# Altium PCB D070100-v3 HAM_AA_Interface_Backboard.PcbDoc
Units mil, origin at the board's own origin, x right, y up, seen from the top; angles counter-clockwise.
Board outline 2600 x 10000 mil, 6 copper layers (Top Layer, InternalPlane1, MidLayer1, InternalPlane3, InternalPlane4, Bottom Layer), stack 92.2 mil thick; 10 components, 66 nets, 166 pads, 190 vias.
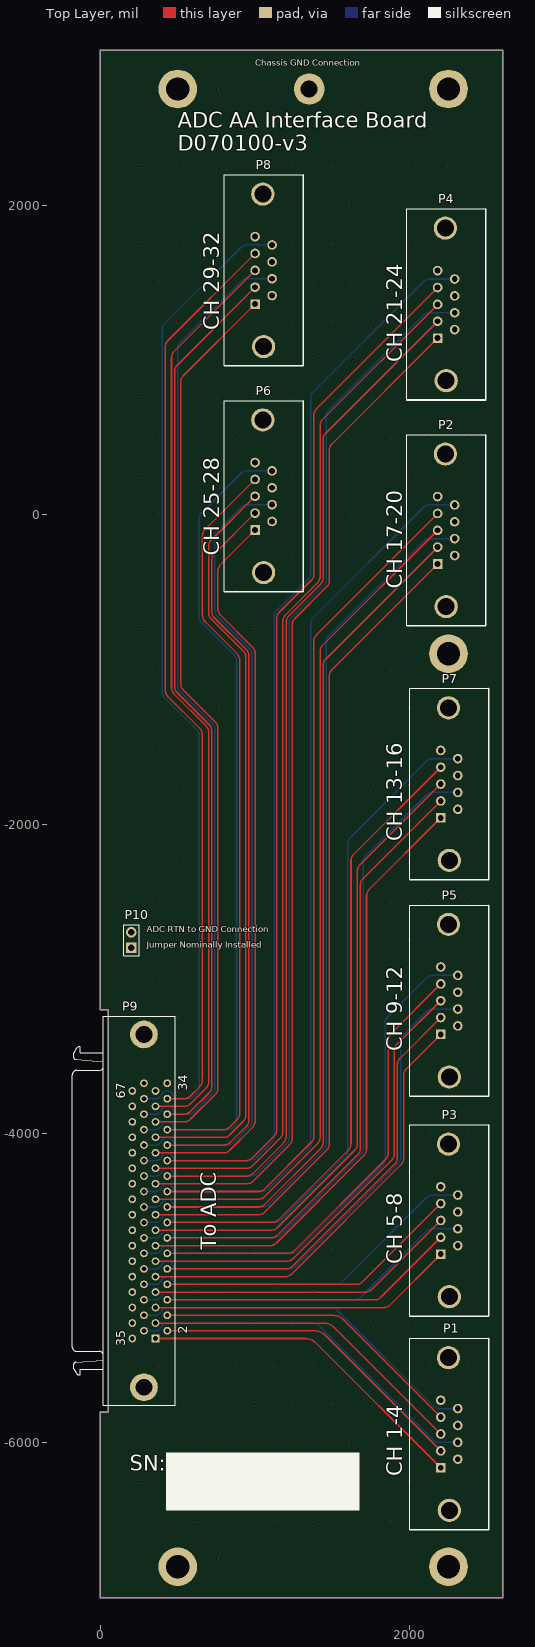
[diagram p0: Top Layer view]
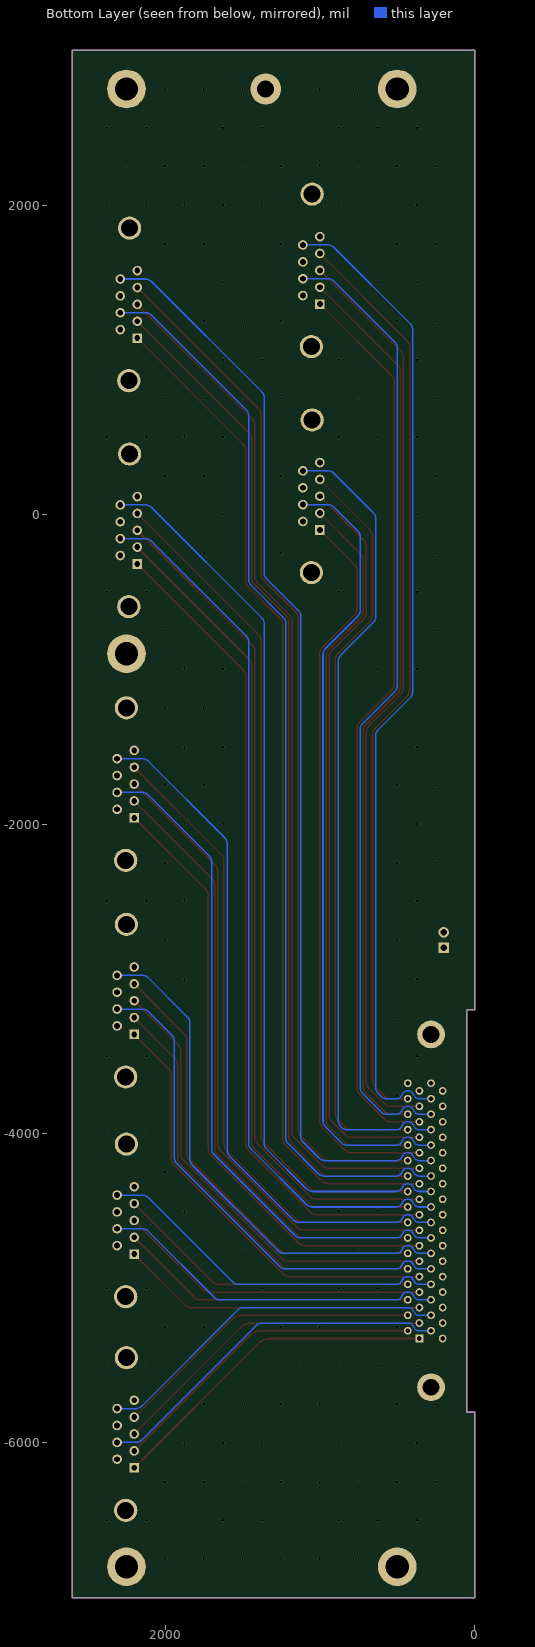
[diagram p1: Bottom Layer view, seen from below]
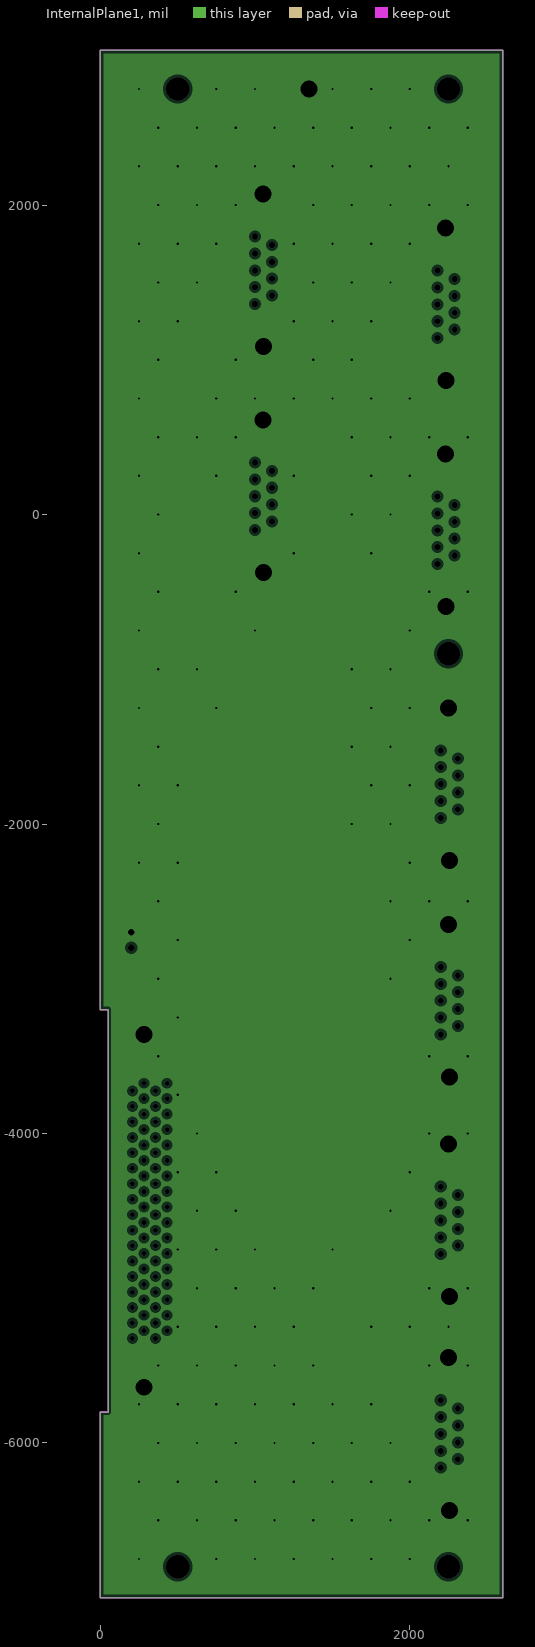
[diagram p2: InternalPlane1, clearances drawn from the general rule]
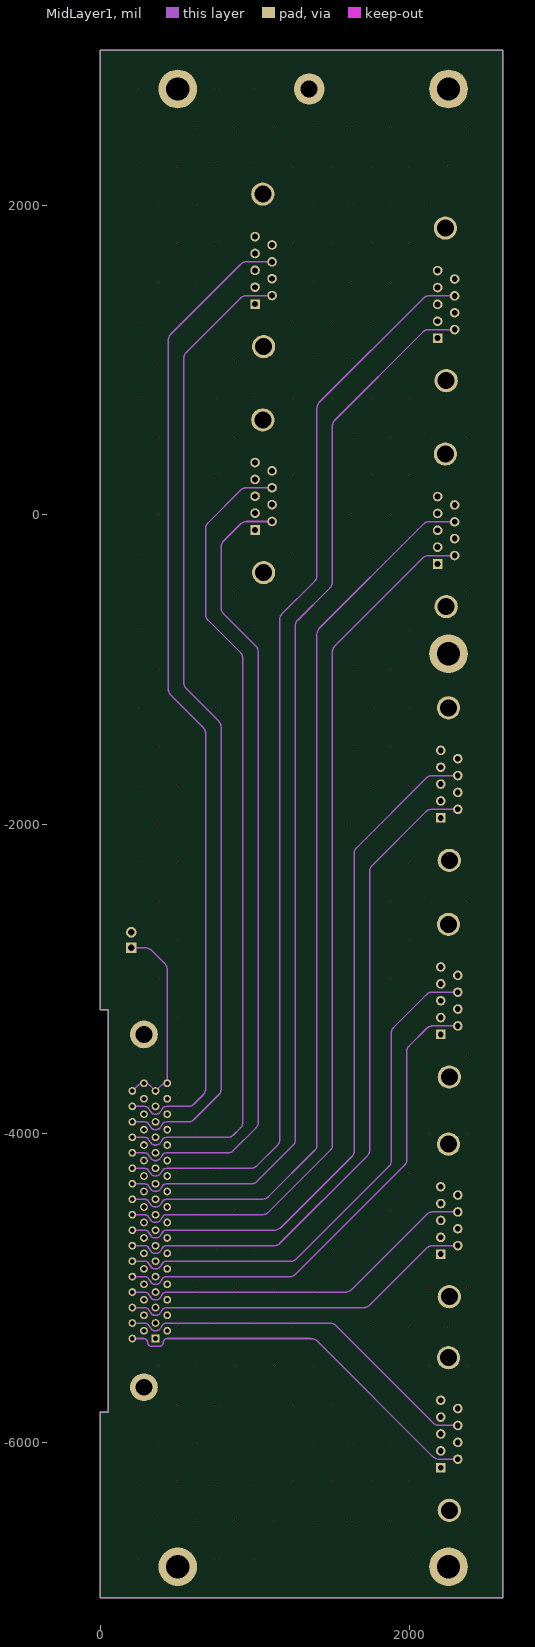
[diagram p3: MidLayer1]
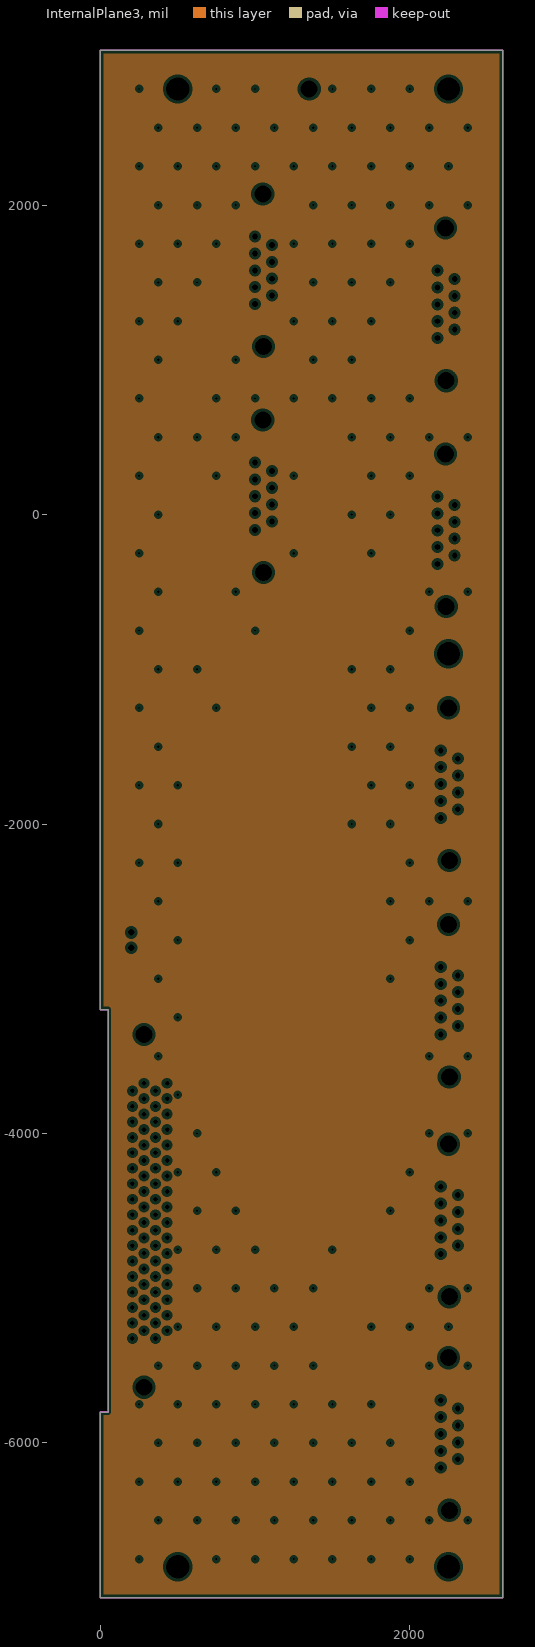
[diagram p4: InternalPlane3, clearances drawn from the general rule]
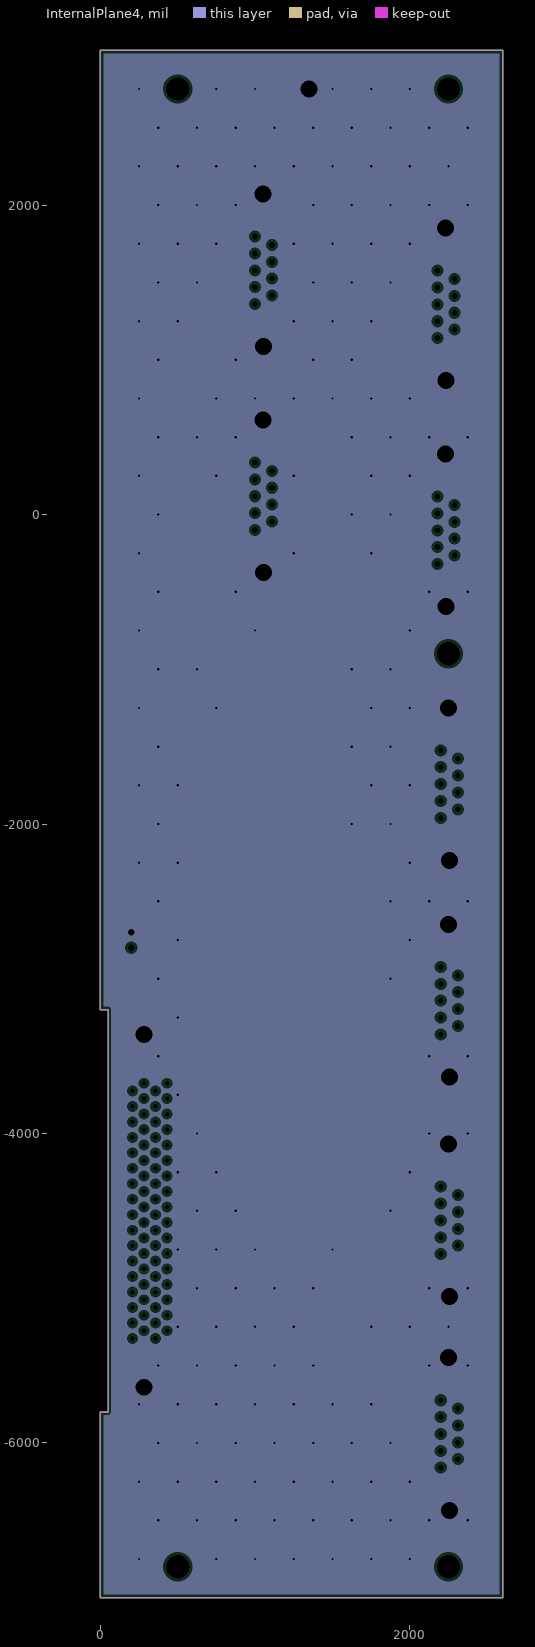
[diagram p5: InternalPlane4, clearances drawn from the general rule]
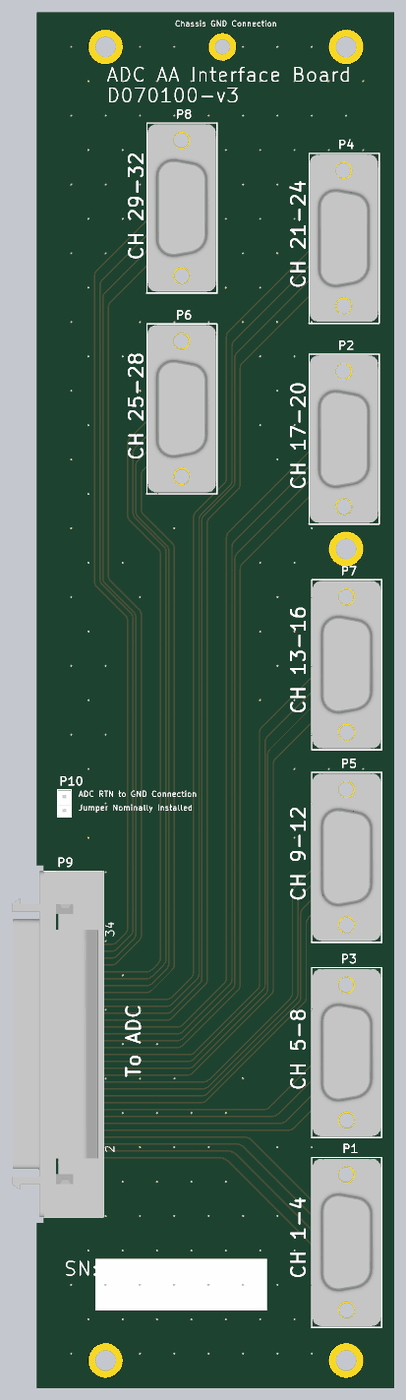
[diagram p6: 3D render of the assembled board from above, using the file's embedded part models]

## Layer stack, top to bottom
Top Solder: solder mask 0.4, Solder Resist, Dk 3.5
Top Layer: signal copper 1.4
Dielectric1: core 15, FR-4, Dk 4.2
InternalPlane1: plane copper 1.4, net GND
Dielectric 6: prepreg 19.4, FR-4, Dk 4.2
MidLayer1: signal copper 1.4
Dielectric3: core 15, FR-4, Dk 4.2
InternalPlane3: plane copper 1.4
Dielectric4: prepreg 19.4, FR-4, Dk 4.2
InternalPlane4: plane copper 1.4, net GND
Dielectric5: core 15, FR-4, Dk 4.2
Bottom Layer: signal copper 1.4
Bottom Solder: solder mask 0.4, Solder Resist, Dk 3.5

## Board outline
0,-7000 0,-5800 50,-5800 50,-3200 0,-3200 0,3000 2600,3000 2600,-7000

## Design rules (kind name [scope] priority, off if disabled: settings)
Clearance [All] p1: gap=10 ignorepadtopadclearanceinfootprint=FALSE except(0: Arc-Hole Track-Hole SMDPad-Hole THPad-Hole Via-Hole Fill-Hole Poly-Hole Region-Hole Text-Hole)
FabricationTestPointUsage TestPointUsage [All] p1: valid=0 allowmultiple=FALSE
FabricationTestpoint Testpoint [All] p1: side=3 testpointundercomponent=TRUE minsize=40 maxsize=100 preferedsize=60 minholesize=0 maxholesize=40 preferedholesize=32 testpointgrid=1 allowsidetop=TRUE allowsidebottom=TRUE usegrid=TRUE gridtolerance=0.01
HoleSize [All] p1: absolutevalues=TRUE maxlimit=200 minlimit=1 maxpercent=80.000 minpercent=20.000
PlaneClearance [All] p1: clearance=20
PlaneConnect [All] p1: planeconnectstyle=Direct reliefexpansion=20 reliefentries=2 reliefconductorwidth=10 reliefairgap=10
PolygonConnect [All] p1: connectstyle=Direct reliefconductorwidth=10 reliefentries=4 polygonreliefangle="90 Angle" airgapwidth=10
RoutingVias [All] p1: holewidth=20 width=40 viastyle="Through Hole" minholewidth=20 minwidth=40 maxholewidth=28 maxwidth=50
SolderMaskExpansion [All] p1: expansion=4
Width [All] p1: maxlimit=100 minlimit=10 preferedwidth=10
25 further rules are at their usual default settings.

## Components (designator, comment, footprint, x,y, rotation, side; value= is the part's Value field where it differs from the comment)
P1 "D9M" DB9/M 2200,-6160 r270 top
P2 "D9M" DB9/M 2180,-320 r270 top
P3 "D9M" DB9/M 2200,-4780 r270 top
P4 "D9M" DB9/M 2180,1140 r270 top
P5 "D9M" DB9/M 2200,-3360 r270 top
P6 "D9M" DB9/M 1000,-100 r270 top
P7 "D9M" DB9/M 2200,-1960 r270 top
P8 "D9M" DB9/M 1000,1360 r270 top
P9 "787082-7" 787082-7 20,-4500 r90 top
P10 "Header 2" HDR1X2 200,-2800 r90 top

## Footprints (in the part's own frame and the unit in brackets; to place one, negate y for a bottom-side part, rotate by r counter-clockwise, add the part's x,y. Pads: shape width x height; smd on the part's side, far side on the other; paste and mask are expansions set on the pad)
787082-7 [mm] "Connector; D Subminiature 050 Series; 68 Position; Right Angle"
  rect 1.27x1.27 hole 0.762: 1(-20.955,-8.555)
  round 1.27 hole 0.762: 2(-19.685,-10.46) 3(-18.415,-8.555) 4(-17.145,-10.46) 5(-15.875,-8.555) 6(-14.605,-10.46) 7(-13.335,-8.555) 8(-12.065,-10.46) 9(-10.795,-8.555) 10(-9.525,-10.46) 11(-8.255,-8.555) 12(-6.985,-10.46) 13(-5.715,-8.555) 14(-4.445,-10.46) 15(-3.175,-8.555) 16(-1.905,-10.46) 17(-0.635,-8.555) 18(0.635,-10.46) 19(1.905,-8.555) 20(3.175,-10.46) 21(4.445,-8.555) 22(5.715,-10.46) 23(6.985,-8.555) 24(8.255,-10.46) 25(9.525,-8.555) 26(10.795,-10.46) 27(12.065,-8.555) 28(13.335,-10.46) 29(14.605,-8.555) 30(15.875,-10.46) 31(17.145,-8.555) 32(18.415,-10.46) 33(19.685,-8.555) 34(20.955,-10.46) 35(-20.955,-4.745) 36(-19.685,-6.65) 37(-18.415,-4.745) 38(-17.145,-6.65) 39(-15.875,-4.745) 40(-14.605,-6.65) 41(-13.335,-4.745) 42(-12.065,-6.65) 43(-10.795,-4.745) 44(-9.525,-6.65) 45(-8.255,-4.745) 46(-6.985,-6.65) 47(-5.715,-4.745) 48(-4.445,-6.65) 49(-3.175,-4.745) 50(-1.905,-6.65) 51(-0.635,-4.745) 52(0.635,-6.65) 53(1.905,-4.745) 54(3.175,-6.65) 55(4.445,-4.745) 56(5.715,-6.65) 57(6.985,-4.745) 58(8.255,-6.65) 59(9.525,-4.745) 60(10.795,-6.65) 61(12.065,-4.745) 62(13.335,-6.65) 63(14.605,-4.745) 64(15.875,-6.65) 65(17.145,-4.745) 66(18.415,-6.65) 67(19.685,-4.745) 68(20.955,-6.65)
  round 4.55 hole 2.77: 69(-28.955,-6.65) 70(28.955,-6.65)
  silkscreen extent -31.95,-11.76 31.95,5.11, body extent -31.94,-11.79 31.94,5.08, height 9.51
DB9/M [mil]
  rect 62x62 hole 38: 1(0,0)
  round 62 hole 38: 2(-109,0) 3(-218,0) 4(-327,0) 5(-436,0) 6(-55,110) 7(-164,110) 8(-273,110) 9(-382,110)
  round 150 hole 110: 10(275,55) 11(-711,50)
  silkscreen extent -836,-200 400,310, body extent -827,-194 389,302, height 470
HDR1X2 [mm] "Connector; Header; 2 Position"
  rect 1.75x1.75 hole 1.1: 1(0,0)
  round 1.75 hole 1.1: 2(2.54,0)
  silkscreen extent -1.27,-1.27 3.81,1.27, body extent -1.14,-1.19 3.68,1.15, height 10.8

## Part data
P1 P2 P3 P4 P5 P6 P7 P8: "9 Position D-Sub Plug, Male Pins Connector", Color=Black, Current Rating=6A, Flammability Rating="UL94 V-0", Manufacturer="TE Connectivity", Manufacturer Part Number=5747871-8, Max Operating Temperature=105°C, Max Supply Voltage (AC)=250V, Max Voltage Rating (DC)=250.25kV, Min Operating Temperature=-55°C, Package Quantity=17, Supplier Part Number 1=A32035-ND, Voltage Rating=125V
P9: library part D68, "68 Position D-Type Receptacle, Female Sockets Connector", Color=Black, Current Rating=1A, Flammability Rating="UL94 V-0", Manufacturer="TE Connectivity", Manufacturer Part Number=7870827, Max Operating Temperature=105°C, Min Operating Temperature=-55°C, Package Quantity=8, Supplier Part Number 1=A3321-ND, Voltage Rating=30V
P10: "Connector Header Through Hole 2 position 0.100\" (2.54mm)", Color=White, Contact Resistance=10mR, Current Rating=4A, Flammability Rating="UL94 V-0", Insulation Resistance=500GR, Manufacturer=Molex, Manufacturer Part Number=22-23-2021, Max Operating Temperature=75°C, Min Operating Temperature=0°C, Package Quantity=3000, Supplier Part Number 1=900-0022232021-ND, Voltage Rating=250V

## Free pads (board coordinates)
  round 200 hole 110: 0(1350,2750)
  round 250 hole 150: 0(2250,-6800) 1(2250,2750) 2(500,2750) 3(500,-6800) 4(2250,-900)

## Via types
v1: diameter 15, hole 15, Top Layer to Bottom Layer, tented both sides, 190 vias

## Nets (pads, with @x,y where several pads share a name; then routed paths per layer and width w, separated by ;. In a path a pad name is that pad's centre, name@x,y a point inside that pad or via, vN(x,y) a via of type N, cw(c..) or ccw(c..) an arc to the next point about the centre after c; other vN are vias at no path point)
GND: P1.10 P1.11 P2.10 P2.11 P3.10 P3.11 P4.10 P4.11 P5.10 P5.11 P6.10 P6.11 P7.10 P7.11 P8.10 P8.11 P9.69 P9.70 P10.2 pad.0@1350,2750
  other v1: 250,-6750 750,-6750 1000,-6750 1250,-6750 1500,-6750 1750,-6750 2000,-6750 375,-6500 625,-6500 875,-6500 1125,-6500 1375,-6500 1625,-6500 1875,-6500 2125,-6500 2375,-6500 250,-6250 500,-6250 750,-6250 1000,-6250 1250,-6250 1500,-6250 1750,-6250 2000,-6250 375,-6000 625,-6000 875,-6000 1125,-6000 1375,-6000 1625,-6000 1875,-6000 250,-5750 500,-5750 750,-5750 1000,-5750 1250,-5750 1500,-5750 1750,-5750 375,-5500 625,-5500 875,-5500 1125,-5500 1375,-5500 2125,-5500 2375,-5500 500,-5250 750,-5250 1000,-5250 1250,-5250 1750,-5250 2000,-5250 2250,-5250 625,-5000 875,-5000 1125,-5000 1375,-5000 2125,-5000 2375,-5000 500,-4750 750,-4750 1000,-4750 1500,-4750 625,-4500 875,-4500 1875,-4500 500,-4250 750,-4250 2000,-4250 625,-4000 2125,-4000 2375,-4000 500,-3750 375,-3500 2125,-3500 2375,-3500 500,-3250 375,-3000 1875,-3000 500,-2750 2000,-2750 375,-2500 1875,-2500 2125,-2500 2375,-2500 250,-2250 500,-2250 2000,-2250 375,-2000 1625,-2000 1875,-2000 250,-1750 500,-1750 1750,-1750 2000,-1750 375,-1500 1625,-1500 1875,-1500 250,-1250 750,-1250 1750,-1250 2000,-1250 375,-1000 625,-1000 1625,-1000 1875,-1000 250,-750 1000,-750 2000,-750 375,-500 875,-500 2125,-500 2375,-500 250,-250 1250,-250 1750,-250 375,0 1625,0 1875,0 250,250 750,250 1250,250 1750,250 2000,250 375,500 625,500 875,500 1625,500 1875,500 2125,500 2375,500 250,750 750,750 1000,750 1250,750 1500,750 1750,750 2000,750 375,1000 875,1000 1375,1000 1625,1000 250,1250 500,1250 1250,1250 1500,1250 1750,1250 375,1500 625,1500 1375,1500 1625,1500 1875,1500 250,1750 500,1750 750,1750 1250,1750 1500,1750 1750,1750 2000,1750 375,2000 625,2000 875,2000 1375,2000 1625,2000 1875,2000 2125,2000 2375,2000 250,2250 500,2250 750,2250 1000,2250 1250,2250 1500,2250 1750,2250 2000,2250 2250,2250 375,2500 625,2500 875,2500 1125,2500 1375,2500 1625,2500 1875,2500 2125,2500 2375,2500 250,2750 750,2750 1000,2750 1500,2750 1750,2750 2000,2750
NetP9_33: P9.33 P9.34 P9.67 P9.68 P10.1 | length 1312.7
  MidLayer1 w10: P10.1 290,-2800 cw(c290,-2860.36) 332.68,-2817.68 415,-2900 cw(c374.41,-2940.59) 431.81,-2940.59 P9.34 ccw(c431.81,-3735.36) 389.13,-3692.68 P9.33 324.49,-3692.68 ccw(c281.81,-3735.36) P9.68 ccw(c281.81,-3735.36) 239.13,-3692.68 P9.67
OUTPUTN1: P1.6 P9.35 | length 2478.2
  MidLayer1 w10: P9.35 280,-5325 cw(c280,-5350) 305,-5350 ccw(c330,-5350) 330,-5375 356.81,-5375 381.81,-5375 ccw(c381.81,-5350) 406.81,-5350 cw(c431.81,-5350) 431.81,-5325 1360,-5325 cw(c1360,-5385.36) 1402.62,-5342.62 ; P1.6 2190,-6105 cw(c2190,-6044.64) 2147.32,-6087.32 1402.68,-5342.68 ; 1402.62,-5342.62 cw(c1360,-5385.36) 1402.68,-5342.68 ; 1402.62,-5342.62 1402.68,-5342.68
OUTPUTN2: P1.7 P9.36 | length 2386.2
  Top Layer w10: P1.7@2310,-6020 P1.7
  Bottom Layer w10: P9.36 355,-5275 ; 356.81,-5275 ccw(c356.81,-5225) 382.3,-5268.01 ; 382.44,-5267.93 406.08,-5232.13 cw(c431.81,-5275) 431.81,-5225 1370,-5225 cw(c1370,-5285.35) 1412.65,-5242.65 2148.35,-5978.35 ccw(c2191,-5935.65) 2191,-5996 P1.7
OUTPUTN3: P1.8 P9.37 | length 2414.3
  MidLayer1 w10: P9.37 280,-5225 ; 281.81,-5225 cw(c281.81,-5275) 307.3,-5231.99 cw(c281.81,-5275) 307.44,-5232.07 ; 307.28,-5231.82 307.44,-5232.07 ; 406.18,-5232.07 382.54,-5267.87 cw(c356.81,-5225) 356.81,-5275 cw(c356.81,-5225) 331.08,-5267.87 307.44,-5232.07 ; 406.32,-5231.99 cw(c431.81,-5275) 431.81,-5225 1480,-5225 cw(c1480,-5285.36) 1522.68,-5242.68 2149.32,-5869.32 ; P1.8 2192,-5887 cw(c2192,-5826.64) 2149.38,-5869.38 ; 2149.32,-5869.32 ccw(c2192,-5826.64) 2149.38,-5869.38 ; 2149.32,-5869.32 2149.38,-5869.38
OUTPUTN4: P1.9 P9.38 | length 2313.4
  Bottom Layer w10: P9.38 355,-5175 ; 356.81,-5175 ccw(c356.81,-5125) 382.3,-5168.01 ; 382.44,-5167.93 406.08,-5132.13 cw(c431.81,-5175) 431.81,-5125 1490,-5125 cw(c1490,-5185.35) 1532.65,-5142.65 ; 1532.68,-5142.68 1535,-5145 2150.35,-5760.35 ccw(c2193,-5717.65) 2193,-5778 P1.9
OUTPUTN5: P3.6 P9.39 | length 2310.9
  MidLayer1 w10: P9.39 280,-5125 ; 281.81,-5125 cw(c281.81,-5175) 307.3,-5131.99 ; 406.18,-5132.07 382.54,-5167.87 cw(c356.81,-5125) 356.81,-5175 cw(c356.81,-5125) 331.08,-5167.87 307.44,-5132.07 ; 406.32,-5131.99 cw(c431.81,-5175) 431.81,-5125 1703.79,-5125 ccw(c1703.79,-5073.79) 1739.98,-5110.02 2108,-4742 ; 2110.86,-4739.14 2108,-4742 ; P3.6 2145,-4725 ccw(c2145,-4773.28) 2110.88,-4739.12 2108,-4742 ; 307.3,-5131.99 cw(c281.81,-5175) 307.44,-5132.07 ; 307.3,-5131.99 cw(c356.81,-5125) 307.28,-5131.82 307.44,-5132.07
OUTPUTN6: P3.7 P9.40 | length 2256.1
  Bottom Layer w10: P9.40 355,-5075 ; 356.81,-5075 ccw(c356.81,-5025) 382.3,-5068.01 ; 481.18,-5067.93 457.54,-5032.13 ccw(c431.81,-5075) 431.81,-5025 ccw(c431.81,-5075) 406.08,-5032.13 382.44,-5067.93 ; 481.32,-5068.01 ccw(c506.81,-5025) 506.81,-5075 1645,-5075 ccw(c1645,-5024.3) 1680.83,-5060.17 1686,-5055 2110.17,-4630.83 cw(c2146,-4666.7) 2146,-4616 P3.7 ; 382.3,-5068.01 ccw(c356.81,-5025) 382.44,-5067.93 ; 382.3,-5068.01 ccw(c431.81,-5075) 382.28,-5068.18 382.44,-5067.93
OUTPUTN7: P3.8 P9.41 | length 2362.5
  MidLayer1 w10: P9.41 280,-5025 ; 281.81,-5025 cw(c281.81,-5075) 307.3,-5031.99 ; 406.18,-5032.07 382.54,-5067.87 cw(c356.81,-5025) 356.81,-5075 cw(c356.81,-5025) 331.08,-5067.87 307.44,-5032.07 ; 406.32,-5031.99 cw(c431.81,-5075) 431.81,-5025 1585,-5025 ccw(c1585,-4971.89) 1622.54,-5009.46 2106,-4526 ; 2110.86,-4521.14 2106,-4526 ; P3.8 2145,-4507 ccw(c2145,-4555.28) 2110.88,-4521.12 2106,-4526 ; 307.3,-5031.99 cw(c281.81,-5075) 307.44,-5032.07 ; 307.3,-5031.99 cw(c356.81,-5025) 307.28,-5031.82 307.44,-5032.07
OUTPUTN8: P3.9 P9.42 | length 2305
  Bottom Layer w10: P9.42 355,-4975 ; 356.81,-4975 ccw(c356.81,-4925) 382.3,-4968.01 ; 481.18,-4967.93 457.54,-4932.13 ccw(c431.81,-4975) 431.81,-4925 ccw(c431.81,-4975) 406.08,-4932.13 382.44,-4967.93 ; 481.32,-4968.01 ccw(c506.81,-4925) 506.81,-4975 1527,-4975 ccw(c1527,-4924.3) 1562.83,-4960.17 2110.17,-4412.83 cw(c2146,-4448.7) 2146,-4398 P3.9 ; 382.3,-4968.01 ccw(c356.81,-4925) 382.44,-4967.93 ; 382.3,-4968.01 ccw(c431.81,-4975) 382.28,-4968.18 382.44,-4967.93
OUTPUTN9: P5.6 P9.43 | length 3245.8
  MidLayer1 w10: P9.43 280,-4925 ; 281.81,-4925 cw(c281.81,-4975) 307.3,-4931.99 ; 406.18,-4932.07 382.54,-4967.87 cw(c356.81,-4925) 356.81,-4975 cw(c356.81,-4925) 331.08,-4967.87 307.44,-4932.07 ; 406.32,-4931.99 cw(c431.81,-4975) 431.81,-4925 1225,-4925 ccw(c1225,-4876.72) 1259.12,-4910.88 ; 1259.14,-4910.86 1970,-4200 ccw(c1945.86,-4175.86) 1980,-4175.86 1980,-3471.21 cw(c2031.21,-3471.21) 1994.99,-3435.01 2110.01,-3319.99 cw(c2146.21,-3356.21) 2146.21,-3305 ; 2150,-3305 2146.21,-3305 ; P5.6 2146.21,-3305 ; 307.3,-4931.99 cw(c356.81,-4925) 307.28,-4931.82 307.44,-4932.07 ; 307.3,-4931.99 cw(c281.81,-4975) 307.44,-4932.07
OUTPUTN10: P5.7 P9.44 | length 3225.1
  Bottom Layer w10: P9.44 355,-4875 ; 356.81,-4875 ccw(c356.81,-4825) 382.3,-4868.01 ; 481.18,-4867.93 457.54,-4832.13 ccw(c431.81,-4875) 431.81,-4825 ccw(c431.81,-4875) 406.08,-4832.13 382.44,-4867.93 ; 481.32,-4868.01 ccw(c506.81,-4825) 506.81,-4875 1224,-4875 ccw(c1224,-4824.3) 1259.83,-4860.17 1925.17,-4194.83 ccw(c1889.3,-4159) 1940,-4159 1940,-3402 cw(c1990.7,-3402) 1954.83,-3366.17 2110.17,-3210.83 cw(c2146,-3246.7) 2146,-3196 P5.7 ; 382.3,-4868.01 ccw(c356.81,-4825) 382.44,-4867.93 ; 382.3,-4868.01 ccw(c431.81,-4875) 382.28,-4868.18 382.44,-4867.93
OUTPUTN11: P5.8 P9.45 | length 3365.1
  MidLayer1 w10: P9.45 280,-4825 ; 281.81,-4825 cw(c281.81,-4875) 307.3,-4831.99 ; 406.18,-4832.07 382.54,-4867.87 cw(c356.81,-4825) 356.81,-4875 cw(c356.81,-4825) 331.08,-4867.87 307.44,-4832.07 ; 406.32,-4831.99 cw(c431.81,-4875) 431.81,-4825 1235,-4825 ccw(c1235,-4783.96) 1264.01,-4812.99 1867.98,-4209.02 ccw(c1838.96,-4180) 1880,-4180 1880,-3351.21 cw(c1931.21,-3351.21) 1894.99,-3315.01 2107.45,-3102.55 cw(c2145,-3140.11) 2145,-3087 P5.8 ; 307.3,-4831.99 cw(c356.81,-4825) 307.28,-4831.82 307.44,-4832.07 ; 307.3,-4831.99 cw(c281.81,-4875) 307.44,-4832.07
OUTPUTN12: P5.9 P9.46 | length 3349
  Bottom Layer w10: P9.46 355,-4775 ; 356.81,-4775 ccw(c356.81,-4725) 382.3,-4768.01 ; 481.18,-4767.93 457.54,-4732.13 ccw(c431.81,-4775) 431.81,-4725 ccw(c431.81,-4775) 406.08,-4732.13 382.44,-4767.93 ; 481.32,-4768.01 ccw(c506.81,-4725) 506.81,-4775 1234,-4775 ccw(c1234,-4724.3) 1269.83,-4760.17 1825.17,-4204.83 ccw(c1789.3,-4169) 1840,-4169 1840,-3284 cw(c1890.7,-3284) 1854.83,-3248.17 2110.17,-2992.83 cw(c2146,-3028.7) 2146,-2978 P5.9 ; 382.3,-4768.01 ccw(c356.81,-4725) 382.44,-4767.93 ; 382.3,-4768.01 ccw(c431.81,-4775) 382.28,-4768.18 382.44,-4767.93
OUTPUTN13: P7.6 P9.47 | length 4398.4
  MidLayer1 w10: P9.47 280,-4725 ; 281.81,-4725 cw(c281.81,-4775) 307.3,-4731.99 ; 406.18,-4732.07 382.54,-4767.87 cw(c356.81,-4725) 356.81,-4775 cw(c356.81,-4725) 331.08,-4767.87 307.44,-4732.07 ; 406.32,-4731.99 cw(c431.81,-4775) 431.81,-4725 1123.79,-4725 ccw(c1123.79,-4673.79) 1159.98,-4710.02 1725.03,-4144.97 ccw(c1688.79,-4108.79) 1740,-4108.81 ; 1740,-4105 1740,-4108.79 ; 1740,-2315 1740,-2306.21 ; 1740,-2306.15 cw(c1791.21,-2306.21) 1740,-2306.07 ; 2141.19,-1905 ccw(c2141.21,-1956.21) 2141.07,-1905 ; P7.6 2141.07,-1905 ; 307.3,-4731.99 cw(c356.81,-4725) 307.28,-4731.82 307.44,-4732.07 ; 307.3,-4731.99 cw(c281.81,-4775) 307.44,-4732.07 ; 1740,-4108.81 1740,-2306.07 ; 1740,-2306.07 cw(c1791.21,-2306.21) 1754.94,-2270.06 cw(c1791.21,-2306.21) 1755,-2270 2105.06,-1919.94 cw(c2141.21,-1956.21) 2141.07,-1905
OUTPUTN14: P7.7 P9.48 | length 4366.6
  Bottom Layer w10: P9.48 355,-4675 ; 356.81,-4675 ccw(c356.81,-4625) 382.3,-4668.01 ; 481.18,-4667.93 457.54,-4632.13 ccw(c431.81,-4675) 431.81,-4625 ccw(c431.81,-4675) 406.08,-4632.13 382.44,-4667.93 ; 481.32,-4668.01 ccw(c506.81,-4625) 506.81,-4675 1124,-4675 ccw(c1124,-4624.3) 1159.83,-4660.17 1685.17,-4134.83 ccw(c1649.3,-4099) 1700,-4099 1700,-2242 cw(c1750.7,-2242) 1714.83,-2206.17 2110.17,-1810.83 cw(c2146,-1846.7) 2146,-1796 P7.7 ; 382.3,-4668.01 ccw(c356.81,-4625) 382.44,-4667.93 ; 382.3,-4668.01 ccw(c431.81,-4675) 382.28,-4668.18 382.44,-4667.93
OUTPUTN15: P7.8 P9.49 | length 4508.1
  MidLayer1 w10: P9.49 280,-4625 ; 281.81,-4625 cw(c281.81,-4675) 307.3,-4631.99 ; 406.18,-4632.07 382.54,-4667.87 cw(c356.81,-4625) 356.81,-4675 cw(c356.81,-4625) 331.08,-4667.87 307.44,-4632.07 ; 406.32,-4631.99 cw(c431.81,-4675) 431.81,-4625 1123.79,-4625 ccw(c1123.79,-4561.72) 1168.46,-4606.54 ; 1170,-4605 1168.54,-4606.46 cw(c1123.79,-4561.72) 1168.46,-4606.54 ; 1640,-2195 1640,-2191.21 ; 2106.53,-1703.47 1655,-2155 ccw(c1691.21,-2191.21) 1640,-2191.2 ; 2108.06,-1701.94 cw(c2144.21,-1738.21) 2144.07,-1687 ; 2144.19,-1687 ccw(c2144.21,-1738.21) 2144.07,-1687 ; P7.8 2144.07,-1687 ; 307.3,-4631.99 cw(c281.81,-4675) 307.44,-4632.07 ; 307.3,-4631.99 cw(c356.81,-4625) 307.28,-4631.82 307.44,-4632.07 ; 1168.46,-4606.54 1625,-4150 1625.86,-4149.14 ccw(c1591.72,-4115) 1640,-4115.01 1640,-2191.21
OUTPUTN16: P7.9 P9.50 | length 4490.4
  Bottom Layer w10: P9.50 355,-4575 ; 356.81,-4575 ccw(c356.81,-4525) 382.3,-4568.01 ; 481.18,-4567.93 457.54,-4532.13 ccw(c431.81,-4575) 431.81,-4525 ccw(c431.81,-4575) 406.08,-4532.13 382.44,-4567.93 ; 481.32,-4568.01 ccw(c506.81,-4525) 506.81,-4575 1134,-4575 ccw(c1134,-4524.3) 1169.83,-4560.17 1585.17,-4144.83 ccw(c1549.3,-4109) 1600,-4109 1600,-2124 cw(c1650.7,-2124) 1614.83,-2088.17 2110.17,-1592.83 cw(c2146,-1628.7) 2146,-1578 P7.9 ; 382.3,-4568.01 ccw(c356.81,-4525) 382.44,-4567.93 ; 382.3,-4568.01 ccw(c431.81,-4575) 382.28,-4568.18 382.44,-4567.93
OUTPUTN17: P2.6 P9.51 | length 5772.2
  MidLayer1 w10: P9.51 280,-4525 ; 281.81,-4525 cw(c281.81,-4575) 307.3,-4531.99 ; 406.18,-4532.07 382.54,-4567.87 cw(c356.81,-4525) 356.81,-4575 cw(c356.81,-4525) 331.08,-4567.87 307.44,-4532.07 ; 406.32,-4531.99 cw(c431.81,-4575) 431.81,-4525 1045,-4525 ccw(c1045,-4467.06) 1085.97,-4508.03 1486.57,-4107.43 ; 1486.59,-4107.41 ccw(c1454.13,-4075) 1500,-4075 1500,-895 1500,-886.21 cw(c1551.21,-886.21) 1514.99,-850.01 2080,-285 2082.32,-282.68 cw(c2125,-325.36) 2125,-265 P2.6 ; 307.3,-4531.99 cw(c281.81,-4575) 307.44,-4532.07 ; 307.3,-4531.99 cw(c356.81,-4525) 307.28,-4531.82 307.44,-4532.07
OUTPUTN18: P2.7 P9.52 | length 5754.3
  Bottom Layer w10: P9.52 355,-4475 ; 356.81,-4475 ccw(c356.81,-4425) 382.3,-4468.01 ; 481.18,-4467.93 457.54,-4432.13 ccw(c431.81,-4475) 431.81,-4425 ccw(c431.81,-4475) 406.08,-4432.13 382.44,-4467.93 ; 481.32,-4468.01 ccw(c506.81,-4425) 506.81,-4475 ; 506.64,-4475 1048.83,-4475 ; 1049,-4475 ccw(c1049,-4424.3) 1084.83,-4460.17 1445.17,-4099.83 ccw(c1409.3,-4064) 1460,-4064 1460,-822 cw(c1510.7,-822) 1474.83,-786.17 2090.17,-170.83 cw(c2126,-206.7) 2126,-156 P2.7 ; 382.3,-4468.01 ccw(c356.81,-4425) 382.44,-4467.93 ; 382.3,-4468.01 ccw(c431.81,-4475) 382.28,-4468.18 382.44,-4467.93
OUTPUTN19: P2.8 P9.53 | length 5898.5
  MidLayer1 w10: P9.53 280,-4425 ; 281.81,-4425 cw(c281.81,-4475) 307.3,-4431.99 ; 406.18,-4432.07 382.54,-4467.87 cw(c356.81,-4425) 356.81,-4475 cw(c356.81,-4425) 331.08,-4467.87 307.44,-4432.07 ; 406.32,-4431.99 cw(c431.81,-4475) 431.81,-4425 1045.25,-4425 ccw(c1045.25,-4365.25) 1087.5,-4407.5 1385.86,-4109.14 ccw(c1351.72,-4075) 1400,-4075.02 1400,-771.21 ; 1400,-780 1400,-771.21 ; P2.8 2120,-47 ccw(c2120,-88.04) 2090.98,-59.02 2085,-65 1415,-735 ccw(c1451.21,-771.21) 1400,-771.19 ; 307.3,-4431.99 cw(c281.81,-4475) 307.44,-4432.07 ; 307.3,-4431.99 cw(c356.81,-4425) 307.28,-4431.82 307.44,-4432.07
OUTPUTN20: P2.9 P9.54 | length 5872.3
  Bottom Layer w10: P9.54 355,-4375 ; 356.81,-4375 ccw(c356.81,-4325) 382.3,-4368.01 ; 481.18,-4367.93 457.54,-4332.13 ccw(c431.81,-4375) 431.81,-4325 ccw(c431.81,-4375) 406.08,-4332.13 382.44,-4367.93 ; 481.32,-4368.01 ccw(c506.81,-4325) 506.81,-4375 1049,-4375 ccw(c1049,-4324.3) 1084.83,-4360.17 1345.17,-4099.83 ccw(c1309.3,-4064) 1360,-4064 1360,-704 cw(c1410.7,-704) 1374.83,-668.17 2090.17,47.17 cw(c2126,11.3) 2126,62 P2.9 ; 382.3,-4368.01 ccw(c356.81,-4325) 382.44,-4367.93 ; 382.3,-4368.01 ccw(c431.81,-4375) 382.28,-4368.18 382.44,-4367.93
OUTPUTN21: P4.6 P9.55 | length 6988.5
  MidLayer1 w10: P9.55 280,-4325 ; 281.81,-4325 cw(c281.81,-4375) 307.3,-4331.99 ; 406.18,-4332.07 382.54,-4367.87 cw(c356.81,-4325) 356.81,-4375 cw(c356.81,-4325) 331.08,-4367.87 307.44,-4332.07 ; 406.32,-4331.99 cw(c431.81,-4375) 431.81,-4325 975,-4325 ccw(c975,-4271.89) 1012.54,-4309.46 1247,-4075 ccw(c1215.62,-4043.62) 1260,-4043.62 ; 1260,-4045 1260,-720 1260,-719.21 cw(c1311.21,-719.21) 1275,-683 1483.75,-474.25 ; 1483,-475 1483.74,-474.26 ; P4.6 2121.21,1195 ccw(c2121.21,1143.79) 2085,1180 1515,610 ccw(c1551.21,573.79) 1500,573.79 1500,-435 cw(c1444.48,-435) 1483.75,-474.25 ; 307.3,-4331.99 cw(c281.81,-4375) 307.44,-4332.07 ; 307.3,-4331.99 cw(c356.81,-4325) 307.28,-4331.82 307.44,-4332.07
OUTPUTN22: P4.7 P9.56 | length 6966.2
  Bottom Layer w10: P9.56 355,-4275 ; 356.81,-4275 ccw(c356.81,-4225) 382.3,-4268.01 ; 481.18,-4267.93 457.54,-4232.13 ccw(c431.81,-4275) 431.81,-4225 ccw(c431.81,-4275) 406.08,-4232.13 382.44,-4267.93 ; 481.32,-4268.01 ccw(c506.81,-4225) 506.81,-4275 974,-4275 ccw(c974,-4224.3) 1009.83,-4260.17 1205.17,-4064.83 ccw(c1169.3,-4029) 1220,-4029 1220,-702.43 cw(c1270.7,-702.43) 1234.76,-666.67 ; 1234.83,-666.6 ccw(c1270.7,-702.43) 1234.76,-666.67 ; 1474.82,673.82 ccw(c1510.7,638) 1460,638 1460,-420.43 cw(c1409.3,-420.43) 1445.17,-456.26 1234.76,-666.67 ; 1474.83,673.83 2090.17,1289.17 cw(c2126,1253.3) 2126,1304 P4.7 ; 382.3,-4268.01 ccw(c356.81,-4225) 382.44,-4267.93 ; 382.3,-4268.01 ccw(c431.81,-4275) 382.28,-4268.18 382.44,-4267.93
OUTPUTN23: P4.8 P9.57 | length 7103.5
  MidLayer1 w10: P9.57 280,-4225 ; 281.81,-4225 cw(c281.81,-4275) 307.3,-4231.99 ; 406.18,-4232.07 382.54,-4267.87 cw(c356.81,-4225) 356.81,-4275 cw(c356.81,-4225) 331.08,-4267.87 307.44,-4232.07 ; 406.32,-4231.99 cw(c431.81,-4275) 431.81,-4225 975,-4225 ccw(c975,-4176.72) 1009.12,-4210.88 ; 1009.14,-4210.86 1145.86,-4074.14 ccw(c1111.72,-4040) 1160,-4040 1160,-675 1160,-672.95 cw(c1199.53,-672.95) 1171.56,-645.02 1381.23,-435.35 ccw(c1335.84,-390) 1400,-390.44 ; 1380,-436.58 1381.21,-435.37 ; 1400,-390 cw(c1335.84,-390) 1400,-390.44 ; P4.8 2124.21,1413 ccw(c2124.21,1361.79) 2088,1398 1415,725 ccw(c1451.21,688.79) 1400,688.79 1400,-380 1400,-390.44 ; 307.3,-4231.99 cw(c356.81,-4225) 307.28,-4231.82 307.44,-4232.07 ; 307.3,-4231.99 cw(c281.81,-4275) 307.44,-4232.07
OUTPUTN24: P4.9 P9.58 | length 7081.4
  Bottom Layer w10: P9.58 355,-4175 ; 356.81,-4175 ccw(c356.81,-4125) 382.3,-4168.01 ; 481.18,-4167.93 457.54,-4132.13 ccw(c431.81,-4175) 431.81,-4125 ccw(c431.81,-4175) 406.08,-4132.13 382.44,-4167.93 ; 481.32,-4168.01 ccw(c506.81,-4125) 506.81,-4175 969,-4175 ccw(c969,-4124.3) 1004.83,-4160.17 1108.09,-4056.91 ccw(c1072.22,-4021.08) 1122.92,-4021.08 1122.92,-658.09 cw(c1173.62,-658.09) 1137.66,-622.35 ; 1137.74,-622.27 ccw(c1173.62,-658.09) 1137.66,-622.35 ; 1374.83,791.83 ccw(c1410.7,756) 1374.69,791.69 ; P4.9 2126,1522 ccw(c2126,1471.3) 2090.17,1507.17 1374.69,791.69 ; 382.3,-4168.01 ccw(c356.81,-4125) 382.44,-4167.93 ; 382.3,-4168.01 ccw(c431.81,-4175) 382.28,-4168.18 382.44,-4167.93 ; 1137.66,-622.35 1345.17,-414.84 ccw(c1309.3,-379.01) 1360,-379.01 1360,756 cw(c1410.7,756) 1374.69,791.69
OUTPUTN25: P6.6 P9.59 | length 5165.2
  MidLayer1 w10: P9.59 280,-4125 ; 281.81,-4125 cw(c281.81,-4175) 307.3,-4131.99 ; 406.18,-4132.07 382.54,-4167.87 cw(c356.81,-4125) 356.81,-4175 cw(c356.81,-4125) 331.08,-4167.87 307.44,-4132.07 ; 406.32,-4131.99 cw(c431.81,-4175) 431.81,-4125 820,-4125 ccw(c820,-4064.64) 862.68,-4107.32 1005.86,-3964.14 ; 1005.88,-3964.12 ccw(c971.72,-3930) 1020,-3930 1020,-2792 1020,-1500 1020,-886.45 ; 1020,-886.66 ccw(c968.79,-886.66) 1020,-886.45 ; P6.6 944.21,-45 ccw(c944.21,-96.21) 908,-60 795,-173 ccw(c831.21,-209.21) 780,-209.21 780,-604.23 ccw(c831.21,-604.23) 795,-640.44 1005,-850.44 cw(c968.79,-886.66) 1020,-886.45 ; 307.3,-4131.99 cw(c281.81,-4175) 307.44,-4132.07 ; 307.3,-4131.99 cw(c356.81,-4125) 307.28,-4131.82 307.44,-4132.07
OUTPUTN26: P6.7 P9.60 | length 5148.4
  Bottom Layer w10: P9.60 355,-4075 ; 356.81,-4075 ccw(c356.81,-4025) 382.3,-4068.01 ; 481.18,-4067.93 457.54,-4032.13 ccw(c431.81,-4075) 431.81,-4025 ccw(c431.81,-4075) 406.08,-4032.13 382.44,-4067.93 ; 481.32,-4068.01 ccw(c506.81,-4025) 506.81,-4075 824,-4075 ccw(c824,-4024.3) 859.83,-4060.17 965.17,-3954.83 ccw(c929.3,-3919) 980,-3919 980,-2785 980,-1500 980,-902.81 ; 980,-903.01 ccw(c929.3,-903.01) 980,-902.81 ; P6.7 946,64 ccw(c946,13.3) 910.17,49.17 754.83,-106.17 ccw(c790.7,-142) 740,-142 740,-621.01 ccw(c790.7,-621.01) 754.83,-656.84 965.17,-867.18 cw(c929.3,-903.01) 980,-902.81 ; 382.3,-4068.01 ccw(c356.81,-4025) 382.44,-4067.93 ; 382.3,-4068.01 ccw(c431.81,-4075) 382.28,-4068.18 382.44,-4067.93
OUTPUTN27: P6.8 P9.61 | length 5283.7
  MidLayer1 w10: P9.61 280,-4025 ; 281.81,-4025 cw(c281.81,-4075) 307.3,-4031.99 ; 406.18,-4032.07 382.54,-4067.87 cw(c356.81,-4025) 356.81,-4075 cw(c356.81,-4025) 331.08,-4067.87 307.44,-4032.07 ; 406.32,-4031.99 cw(c431.81,-4075) 431.81,-4025 825,-4025 ccw(c825,-3976.72) 859.12,-4010.88 ; 859.14,-4010.86 905.01,-3964.99 ccw(c868.79,-3928.79) 920,-3928.79 920,-2777.5 920,-1500 920,-927.85 ; 920,-928.08 ccw(c868.79,-928.08) 920,-927.85 ; P6.8 944.21,173 ccw(c944.21,121.79) 908,158 695,-55 ccw(c731.21,-91.21) 680,-91.21 680,-645.65 ccw(c731.21,-645.65) 695,-681.86 905,-891.86 cw(c868.79,-928.08) 920,-927.85 ; 307.3,-4031.99 cw(c281.81,-4075) 307.44,-4032.07 ; 307.3,-4031.99 cw(c356.81,-4025) 307.28,-4031.82 307.44,-4032.07
OUTPUTN28: P6.9 P9.62 | length 5266.2
  Bottom Layer w10: P9.62 355,-3975 ; 356.81,-3975 ccw(c356.81,-3925) 382.3,-3968.01 ; 481.18,-3967.93 457.54,-3932.13 ccw(c431.81,-3975) 431.81,-3925 ccw(c431.81,-3975) 406.08,-3932.13 382.44,-3967.93 ; 481.32,-3968.01 ccw(c506.81,-3925) 506.81,-3975 824,-3975 ccw(c824,-3924.3) 859.83,-3960.17 865.17,-3954.83 ccw(c829.3,-3919) 880,-3919 880,-2715.75 880,-1500 880,-944.43 ccw(c829.3,-944.43) 865.17,-908.6 654.83,-698.26 cw(c690.7,-662.43) 640,-662.43 640,-24 cw(c690.7,-24) 654.83,11.83 910.17,267.17 cw(c946,231.3) 946,282 P6.9 ; 382.3,-3968.01 ccw(c356.81,-3925) 382.44,-3967.93 ; 382.3,-3968.01 ccw(c431.81,-3975) 382.28,-3968.18 382.44,-3967.93
OUTPUTN29: P8.6 P9.63 | length 6280
  MidLayer1 w10: P9.63 280,-3925 ; 281.81,-3925 cw(c281.81,-3975) 307.3,-3931.99 ; 406.18,-3932.07 382.54,-3967.87 cw(c356.81,-3925) 356.81,-3975 cw(c356.81,-3925) 331.08,-3967.87 307.44,-3932.07 ; 406.32,-3931.99 cw(c431.81,-3975) 431.81,-3925 570,-3925 ccw(c570,-3876.72) 604.12,-3910.88 ; 604.14,-3910.86 765.86,-3749.14 ccw(c731.72,-3715) 780,-3715.01 780,-1371.21 ; 780,-1375 780,-1371.21 ; P8.6 944.21,1415 ccw(c944.21,1363.79) 908,1400 555,1047 ccw(c591.21,1010.79) 540,1010.81 540,-1088.79 ccw(c591.21,-1088.79) 555,-1125 765,-1335 cw(c728.79,-1371.21) 780,-1371.21 ; 307.3,-3931.99 cw(c356.81,-3925) 307.28,-3931.82 307.44,-3932.07 ; 307.3,-3931.99 cw(c281.81,-3975) 307.44,-3932.07
OUTPUTN30: P8.7 P9.64 | length 6259
  Bottom Layer w10: P9.64 355,-3875 ; 356.81,-3875 ccw(c356.81,-3825) 382.3,-3868.01 ; 481.18,-3867.93 457.54,-3832.13 ccw(c431.81,-3875) 431.81,-3825 ccw(c431.81,-3875) 406.08,-3832.13 382.44,-3867.93 ; 481.32,-3868.01 ccw(c506.81,-3825) 506.81,-3875 569,-3875 ccw(c569,-3824.3) 604.83,-3860.17 725.17,-3739.83 ccw(c689.3,-3704) 740,-3704.1 ; 740,-3704 cw(c689.3,-3704) 740,-3704.1 ; P8.7 946,1524 ccw(c946,1473.3) 910.17,1509.17 514.83,1113.83 ccw(c550.7,1078) 500,1078 500,-1105.57 ccw(c550.7,-1105.57) 514.83,-1141.4 725.17,-1351.74 cw(c689.3,-1387.57) 740,-1387.57 740,-3704.1 ; 382.3,-3868.01 ccw(c356.81,-3825) 382.44,-3867.93 ; 382.3,-3868.01 ccw(c431.81,-3875) 382.28,-3868.18 382.44,-3867.93
OUTPUTN31: P8.8 P9.65 | length 6394.1
  MidLayer1 w10: P9.65 280,-3825 ; 281.81,-3825 cw(c281.81,-3875) 307.3,-3831.99 ; 406.18,-3832.07 382.54,-3867.87 cw(c356.81,-3825) 356.81,-3875 cw(c356.81,-3825) 331.08,-3867.87 307.44,-3832.07 ; 406.32,-3831.99 cw(c431.81,-3875) 431.81,-3825 570,-3825 ccw(c570,-3776.72) 604.12,-3810.88 ; 604.14,-3810.86 665.03,-3749.97 ccw(c628.79,-3713.79) 680,-3713.8 680,-1412.63 ccw(c628.79,-1412.63) 665,-1376.42 455,-1166.42 cw(c491.21,-1130.21) 440,-1130.21 440,-1125 440,1050 440,1128.79 cw(c491.21,1128.79) 455,1165 908,1618 cw(c944.21,1581.79) 944.21,1633 P8.8 ; 307.3,-3831.99 cw(c356.81,-3825) 307.28,-3831.82 307.44,-3832.07 ; 307.3,-3831.99 cw(c281.81,-3875) 307.44,-3832.07
OUTPUTN32: P8.9 P9.66 | length 6377
  Bottom Layer w10: P9.66 355,-3775 ; 356.81,-3775 ccw(c356.81,-3725) 382.3,-3768.01 ; 481.18,-3767.93 457.54,-3732.13 ccw(c431.81,-3775) 431.81,-3725 ccw(c431.81,-3775) 406.08,-3732.13 382.44,-3767.93 ; 481.32,-3768.01 ccw(c506.81,-3725) 506.81,-3775 569,-3775 ccw(c569,-3724.3) 604.83,-3760.17 625.17,-3739.83 ccw(c589.3,-3704) 640,-3704.1 ; 640,-3704 cw(c589.3,-3704) 640,-3704.1 ; P8.9 946,1742 ccw(c946,1691.3) 910.17,1727.17 414.83,1231.83 ccw(c450.7,1196) 400,1196 400,-1146.99 ccw(c450.7,-1146.99) 414.83,-1182.82 625.17,-1393.16 cw(c589.3,-1428.99) 640,-1428.99 640,-3704.1 ; 382.3,-3768.01 ccw(c356.81,-3725) 382.44,-3767.93 ; 382.3,-3768.01 ccw(c431.81,-3775) 382.28,-3768.18 382.44,-3767.93
OUTPUTP1: P1.1 P9.1 | length 2184.8
  Top Layer w10: P9.1 1323.58,-5325 cw(c1323.58,-5425) 1394.29,-5354.29 P1.1
OUTPUTP2: P1.2 P9.2 | length 2085.3
  Top Layer w10: P9.2 1382.58,-5275 cw(c1382.58,-5375) 1453.29,-5304.29 P1.2
OUTPUTP3: P1.3 P9.3 | length 2135.9
  Top Layer w10: P9.3 1441.58,-5225 cw(c1441.58,-5325) 1512.29,-5254.29 P1.3
OUTPUTP4: P1.4 P9.4 | length 2036.4
  Top Layer w10: P9.4 1500.58,-5175 cw(c1500.58,-5275) 1571.29,-5204.29 P1.4
OUTPUTP5: P3.1 P9.5 | length 1983.9
  Top Layer w10: P9.5 1832.11,-5125 ; 1832,-5125 ccw(c1832,-5069.47) 1832.11,-5125 ; P3.1 1871.26,-5108.74 ; 1832.11,-5125 ccw(c1832,-5069.47) 1871.2,-5108.8 ; 1871.2,-5108.8 ccw(c1832,-5069.47) 1871.26,-5108.74 ; 1871.2,-5108.8 1871.26,-5108.74
OUTPUTP6: P3.2 P9.6 | length 1933.2
  Top Layer w10: P9.6 1773,-5075 ccw(c1773,-5019.47) 1812.2,-5058.8 ; P3.2 1812.26,-5058.74 ; 1812.2,-5058.8 ccw(c1773,-5019.47) 1812.26,-5058.74 ; 1812.2,-5058.8 1812.26,-5058.74
OUTPUTP7: P3.3 P9.7 | length 2032.7
  Top Layer w10: P9.7 1714,-5025 ccw(c1714,-4969.47) 1753.2,-5008.8 ; P3.3 1753.26,-5008.74 ; 1753.2,-5008.8 ccw(c1714,-4969.47) 1753.26,-5008.74 ; 1753.2,-5008.8 1753.26,-5008.74
OUTPUTP8: P3.4 P9.8 | length 1982.1
  Top Layer w10: P9.8 1655,-4975 ccw(c1655,-4919.47) 1694.2,-4958.8 ; P3.4 1694.26,-4958.74 ; 1694.2,-4958.8 ccw(c1655,-4919.47) 1694.26,-4958.74 ; 1694.2,-4958.8 1694.26,-4958.74
OUTPUTP9: P5.1 P9.9 | length 2827
  Top Layer w10: P9.9 1197,-4925 ccw(c1197,-4869.47) 1236.26,-4908.74 1943.74,-4201.26 ; P5.1 1976.26,-3583.74 ccw(c2015.53,-3623) 1960,-3623 1960,-4162 cw(c1904.47,-4162) 1943.8,-4201.2 ; 1943.74,-4201.26 ccw(c1904.47,-4162) 1943.8,-4201.2 ; 1943.74,-4201.26 1943.8,-4201.2
OUTPUTP10: P5.2 P9.10 | length 2817
  Top Layer w10: P9.10 1202,-4875 ccw(c1202,-4819.47) 1241.26,-4858.74 1903.74,-4196.26 ; 1920,-4160 1920,-3554 cw(c1975.53,-3554) 1936.26,-3514.74 P5.2 ; 1920,-4157 cw(c1864.47,-4157) 1903.8,-4196.2 ; 1903.74,-4196.26 ccw(c1864.47,-4157) 1903.8,-4196.2 ; 1903.74,-4196.26 1903.8,-4196.2
OUTPUTP11: P5.3 P9.11 | length 2950.5
  Top Layer w10: P9.11 1207,-4825 ccw(c1207,-4769.47) 1246.26,-4808.74 1883.74,-4171.26 ; 1900,-4132 cw(c1844.47,-4132) 1899.61,-4138.58 cw(c1844.47,-4132) 1883.8,-4171.2 ; 1900,-4131.61 1900,-3465 cw(c1955.53,-3465) 1916.26,-3425.74 P5.3 ; 1883.74,-4171.26 ccw(c1844.47,-4132) 1883.8,-4171.2 ; 1883.74,-4171.26 1883.8,-4171.2
OUTPUTP12: P5.4 P9.12 | length 2938.4
  Top Layer w10: P9.12 1213,-4775 ccw(c1213,-4719.47) 1252.26,-4758.74 1843.74,-4167.26 ; P5.4 1876.26,-3356.74 ccw(c1915.53,-3396) 1860,-3396 1860,-4128 cw(c1804.47,-4128) 1843.8,-4167.2 ; 1843.74,-4167.26 ccw(c1804.47,-4128) 1843.8,-4167.2 ; 1843.74,-4167.26 1843.8,-4167.2
OUTPUTP13: P7.1 P9.13 | length 3968.5
  Top Layer w10: P9.13 1097,-4725 ccw(c1097,-4669.47) 1136.26,-4708.74 1703.74,-4141.26 ; P7.1 1736.26,-2423.74 ccw(c1775.53,-2463) 1720,-2463 1720,-4102 cw(c1664.47,-4102) 1703.8,-4141.2 ; 1703.74,-4141.26 ccw(c1664.47,-4102) 1703.8,-4141.2 ; 1703.74,-4141.26 1703.8,-4141.2
OUTPUTP14: P7.2 P9.14 | length 3954.6
  Top Layer w10: P9.14 1102,-4675 ccw(c1102,-4619.47) 1141.26,-4658.74 1663.74,-4136.26 ccw(c1624.47,-4097) 1680,-4097.01 ; 1680,-4095 1680,-2392.82 ; 1680,-2393.99 1680,-2392.92 cw(c1732.92,-2392.92) 1680,-2392.82 ; P7.2 1695.5,-2355.5 ccw(c1732.92,-2392.92) 1680,-2392.82
OUTPUTP15: P7.3 P9.15 | length 4090.5
  Top Layer w10: P9.15 1104,-4625 ccw(c1104,-4569.47) 1143.26,-4608.74 1643.74,-4108.26 ccw(c1604.47,-4069) 1660,-4069 1660,-2305 cw(c1715.53,-2305) 1676.26,-2265.74 P7.3
OUTPUTP16: P7.4 P9.16 | length 4079.2
  Top Layer w10: P9.16 1112,-4575 ccw(c1112,-4519.47) 1151.26,-4558.74 1603.74,-4106.26 ; P7.4 1636.26,-2196.74 ccw(c1675.53,-2236) 1620,-2236 1620,-4067 cw(c1564.47,-4067) 1603.8,-4106.2 ; 1603.74,-4106.26 ccw(c1564.47,-4067) 1603.8,-4106.2 ; 1603.74,-4106.26 1603.8,-4106.2
OUTPUTP17: P2.1 P9.17 | length 5356.2
  Top Layer w10: P9.17 1022,-4525 ccw(c1022,-4469.47) 1061.26,-4508.74 1463.74,-4106.26 ; P2.1 1496.26,-1003.74 ccw(c1535.53,-1043) 1480,-1043 1480,-4067 cw(c1424.47,-4067) 1463.8,-4106.2 ; 1463.74,-4106.26 ccw(c1424.47,-4067) 1463.8,-4106.2 ; 1463.74,-4106.26 1463.8,-4106.2
OUTPUTP18: P2.2 P9.18 | length 5343.3
  Top Layer w10: P9.18 1022.15,-4475 ; 1022,-4475 ccw(c1022,-4419.47) 1022.15,-4475 ; 1024.89,-4475 ccw(c1024.89,-4419.47) 1025.04,-4475 1022.15,-4475 ; P2.2 1456.26,-934.74 ccw(c1495.53,-974) 1440,-974 1440,-4057 cw(c1384.47,-4057) 1423.74,-4096.26 1061.26,-4458.74 cw(c1022,-4419.47) 1022.15,-4475
OUTPUTP19: P2.3 P9.19 | length 5474.2
  Top Layer w10: P9.19 1022,-4425 ccw(c1022,-4369.47) 1061.26,-4408.74 1403.74,-4066.26 ccw(c1364.47,-4027) 1420,-4027 1420,-885 cw(c1475.53,-885) 1436.26,-845.74 P2.3
OUTPUTP20: P2.4 P9.20 | length 5458.7
  Top Layer w10: P9.20 1023,-4375 ccw(c1023,-4319.47) 1062.2,-4358.8 1363.74,-4057.26 ccw(c1324.47,-4018) 1380,-4018 1380,-816 cw(c1435.53,-816) 1396.26,-776.74 P2.4
OUTPUTP21: P4.1 P9.21 | length 6567.9
  Top Layer w10: P9.21 947,-4325 ccw(c947,-4269.47) 986.2,-4308.8 ; 986.26,-4308.74 1223.74,-4071.26 ; 1256.26,-673.45 ccw(c1295.53,-712.72) 1256.18,-673.54 ; 1480,417 cw(c1535.53,417) 1480,417.33 ; P4.1 1496.26,456.26 ccw(c1535.53,417) 1480,417.33 ; 1223.74,-4071.26 ccw(c1184.47,-4032) 1223.8,-4071.2 ; 1223.74,-4071.26 1223.8,-4071.2 ; 1223.8,-4071.2 ccw(c1184.47,-4032) 1240,-4032 1240,-712.72 cw(c1295.53,-712.72) 1256.18,-673.54 ; 1256.18,-673.54 1463.74,-465.98 ccw(c1424.47,-426.71) 1480,-426.71 1480,417.33
OUTPUTP22: P4.2 P9.22 | length 6551.6
  Top Layer w10: P9.22 947,-4275 ccw(c947,-4219.47) 986.2,-4258.8 986.26,-4258.74 1183.74,-4061.26 ; P4.2 1456.26,525.26 ccw(c1495.53,486) 1440,486 1440,-410.15 cw(c1384.47,-410.15) 1423.76,-449.38 1216.24,-656.91 ccw(c1255.53,-696.15) 1200,-696.15 1200,-4022 cw(c1144.47,-4022) 1183.8,-4061.2 ; 1183.74,-4061.26 ccw(c1144.47,-4022) 1183.8,-4061.2 ; 1183.74,-4061.26 1183.8,-4061.2
OUTPUTP23: P4.3 P9.23 | length 6683.8
  Top Layer w10: P9.23 944,-4225 ccw(c944,-4169.47) 983.2,-4208.8 983.26,-4208.74 1163.73,-4028.27 ccw(c1124.47,-3989) 1180,-3989 1180,-687.86 cw(c1235.53,-687.86) 1196.24,-648.62 1403.76,-441.1 ccw(c1364.47,-401.86) 1420,-401.86 1420,575 cw(c1475.53,575) 1436.26,614.26 P4.3
OUTPUTP24: P4.4 P9.24 | length 6666.8
  Top Layer w10: P9.24 942,-4175 ccw(c942,-4119.47) 981.2,-4158.8 981.26,-4158.74 1123.74,-4016.26 ; 1156.26,-632.03 ccw(c1195.53,-671.29) 1156.16,-632.14 ; P4.4 1396.27,683.27 ccw(c1435.53,644) 1384.99,667 ccw(c1435.53,644) 1380,644 1380,-385.29 cw(c1324.47,-385.29) 1363.74,-424.56 1156.16,-632.14 ; 1123.74,-4016.26 ccw(c1084.47,-3977) 1123.8,-4016.2 ; 1123.74,-4016.26 1123.8,-4016.2 ; 1123.8,-4016.2 ccw(c1084.47,-3977) 1140,-3977 1140,-671.29 cw(c1195.53,-671.29) 1156.16,-632.14
OUTPUTP25: P6.1 P9.25 | length 4750
  Top Layer w10: P9.25 797,-4125 ccw(c797,-4069.47) 836.2,-4108.8 ; 1000,-896.73 ccw(c944.47,-896.73) 1000,-896.52 ; P6.1 776.26,-323.74 ccw(c815.53,-363) 760,-363 760,-610.73 ccw(c815.53,-610.73) 776.26,-649.99 983.74,-857.46 cw(c944.47,-896.73) 1000,-896.52 ; 836.2,-4108.8 ccw(c797,-4069.47) 836.26,-4108.74 ; 836.2,-4108.8 836.26,-4108.74 ; 836.26,-4108.74 983.74,-3961.26 ; 983.74,-3961.26 ccw(c944.47,-3922) 983.8,-3961.2 ; 983.74,-3961.26 983.8,-3961.2 ; 983.8,-3961.2 ccw(c944.47,-3922) 1000,-3922 1000,-2805.11 1000,-1500 1000,-896.52
OUTPUTP26: P6.2 P9.26 | length 4733.2
  Top Layer w10: P9.26 798.81,-4075 ccw(c798.81,-4019.47) 838.01,-4058.8 ; 942.62,-872.92 736.26,-666.56 cw(c775.53,-627.29) 720,-627.29 720,-294 cw(c775.53,-294) 736.26,-254.74 P6.2 ; 943.74,-874.03 cw(c904.47,-913.3) 960,-913.3 960,-3913.81 cw(c904.47,-3913.81) 943.74,-3953.07 838.07,-4058.74 ; 838.01,-4058.8 ccw(c798.81,-4019.47) 838.07,-4058.74 ; 838.01,-4058.8 838.07,-4058.74
OUTPUTP27: P6.3 P9.27 | length 4867.7
  Top Layer w10: P9.27 797,-4025 ccw(c797,-3969.47) 836.2,-4008.8 ; P6.3 716.26,-165.74 ccw(c755.53,-205) 700,-205 700,-635.58 ccw(c755.53,-635.58) 716.26,-674.84 923.74,-882.32 cw(c884.47,-921.58) 940,-921.58 940,-3882 cw(c884.47,-3882) 923.74,-3921.26 836.26,-4008.74 ; 836.2,-4008.8 ccw(c797,-3969.47) 836.26,-4008.74 ; 836.2,-4008.8 836.26,-4008.74
OUTPUTP28: P6.4 P9.28 | length 4851.9
  Top Layer w10: P9.28 797,-3975 ccw(c797,-3919.47) 836.26,-3958.74 883.74,-3911.26 ccw(c844.47,-3872) 900,-3872 900,-938.04 ; 900,-938.15 ccw(c844.47,-938.15) 900,-938.04 ; P6.4 676.26,-96.74 ccw(c715.53,-136) 660,-136 660,-652.15 ccw(c715.53,-652.15) 676.26,-691.41 883.74,-898.88 ; 883.74,-898.88 cw(c844.47,-938.15) 883.82,-898.97 ; 883.74,-898.88 883.82,-898.97 ; 883.82,-898.97 cw(c844.47,-938.15) 900,-938.04
OUTPUTP29: P8.1 P9.29 | length 5860.5
  Top Layer w10: P9.29 542,-3925 ccw(c542,-3869.47) 581.2,-3908.8 ; 760,-3707 cw(c704.47,-3707) 760,-3707.11 ; P8.1 536.26,896.26 ccw(c575.53,857) 520,857 520,-1095.28 ccw(c575.53,-1095.28) 536.26,-1134.55 743.74,-1342.02 cw(c704.47,-1381.28) 760,-1381.28 760,-3707.11 ; 581.2,-3908.8 ccw(c542,-3869.47) 581.26,-3908.74 ; 581.2,-3908.8 581.26,-3908.74 ; 581.26,-3908.74 743.74,-3746.26 ; 743.74,-3746.26 ccw(c704.47,-3707) 743.8,-3746.2 ; 743.74,-3746.26 743.8,-3746.2 ; 743.8,-3746.2 ccw(c704.47,-3707) 760,-3707.11
OUTPUTP30: P8.2 P9.30 | length 5844.3
  Top Layer w10: P9.30 542,-3875 ccw(c542,-3819.47) 581.26,-3858.74 703.74,-3736.26 ccw(c664.47,-3697) 720,-3697.01 720,-1397.85 ccw(c664.47,-1397.85) 703.74,-1358.59 496.26,-1151.12 cw(c535.53,-1111.85) 480,-1111.85 480,926 cw(c535.53,926) 496.26,965.26 P8.2
OUTPUTP31: P8.3 P9.31 | length 5976.7
  Top Layer w10: P9.31 542,-3825 ccw(c542,-3769.47) 581.26,-3808.74 683.74,-3706.26 ccw(c644.47,-3667) 700,-3667.01 700,-1406.14 ccw(c644.47,-1406.14) 683.74,-1366.87 476.26,-1159.4 cw(c515.53,-1120.14) 460,-1120.14 ; 460,-1118.56 460,1015 cw(c515.53,1015) 476.26,1054.26 P8.3
OUTPUTP32: P8.4 P9.32 | length 5962.5
  Top Layer w10: 420,1084 cw(c475.53,1084) 420,1084.1 ; P9.32 542,-3775 ccw(c542,-3719.47) 581.26,-3758.74 643.74,-3696.26 ccw(c604.47,-3657) 660,-3657.11 ; 660,-3657 cw(c604.47,-3657) 660,-3657.11 ; P8.4 436.26,1123.26 ccw(c475.53,1084) 420,1084.1 ; 420,1084.1 420,-1136.71 ccw(c475.53,-1136.71) 436.26,-1175.97 643.74,-1383.44 cw(c604.47,-1422.71) 660,-1422.71 660,-3657.11
pads on no net: P1.5 P2.5 P3.5 P4.5 P5.5 P6.5 P7.5 P8.5

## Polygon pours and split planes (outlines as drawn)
GND on InternalPlane1 (split plane): 2579.9,-6979.9 20.1,-6979.9 20.1,-5820.1 50,-5820.1 53.92,-5819.71 57.69,-5818.57 61.17,-5816.71 64.21,-5814.21 66.71,-5811.17 68.57,-5807.69 69.71,-5803.92 70.1,-5800 70.1,-3200 69.71,-3196.08 68.57,-3192.31 66.71,-3188.83 64.21,-3185.79 61.17,-3183.29 57.69,-3181.43 53.92,-3180.29 50,-3179.9 20.1,-3179.9 20.1,2979.9 2579.9,2979.9
no net on InternalPlane3 (split plane): 2579.9,-6979.9 20.1,-6979.9 20.1,-5820.1 50,-5820.1 53.92,-5819.71 57.69,-5818.57 61.17,-5816.71 64.21,-5814.21 66.71,-5811.17 68.57,-5807.69 69.71,-5803.92 70.1,-5800 70.1,-3200 69.71,-3196.08 68.57,-3192.31 66.71,-3188.83 64.21,-3185.79 61.17,-3183.29 57.69,-3181.43 53.92,-3180.29 50,-3179.9 20.1,-3179.9 20.1,2979.9 2579.9,2979.9
GND on InternalPlane4 (split plane): 2579.9,-6979.9 20.1,-6979.9 20.1,-5820.1 50,-5820.1 53.92,-5819.71 57.69,-5818.57 61.17,-5816.71 64.21,-5814.21 66.71,-5811.17 68.57,-5807.69 69.71,-5803.92 70.1,-5800 70.1,-3200 69.71,-3196.08 68.57,-3192.31 66.71,-3188.83 64.21,-3185.79 61.17,-3183.29 57.69,-3181.43 53.92,-3180.29 50,-3179.9 20.1,-3179.9 20.1,2979.9 2579.9,2979.9

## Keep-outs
Keep-Out Layer:
  the board outline again, w10

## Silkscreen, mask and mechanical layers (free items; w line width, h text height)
Top Overlay:
  rectangle: 425,-6437.5 1675,-6062.5
  text "Chassis GND Connection" at 1000,2900 h40
  text "ADC AA Interface Board" at 500,2500 h100
  text "D070100-v3" at 500,2350 h100
  text "CH 29-32" at 770,1190 h100 r90
  text "CH 21-24" at 1950,985 h100 r90
  text "CH 25-28" at 770,-265 h100 r90
  text "CH 17-20" at 1950,-480 h100 r90
  text "CH 13-16" at 1950,-2110 h100 r90
  text "ADC RTN to GND Connection" at 300,-2700 h40
  text "Jumper Nominally Installed" at 300,-2800 h40
  text "CH 9-12" at 1950,-3470 h100 r90
  text "To ADC" at 750,-4750 h100 r90
  text "CH 5-8" at 1950,-4845 h100 r90
  text "SN:" at 190,-6180 h100
  text "CH 1-4" at 1950,-6215 h100 r90
Mechanical 1:
  lines w10: 0,-7000 2600,-7000 2600,3000 0,3000 0,-3200 50,-3200 50,-4500 50,-5800 0,-5800 0,-6500

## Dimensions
500,2750 to 0,3000 on Mechanical 1
2250,2750 to 2250,-6800 on Mechanical 1
500,2750 to 2250,2750 on Mechanical 1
